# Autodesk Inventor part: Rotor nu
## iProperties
Shininess: 64.0
Length Units: 11269
Angle Units: 11279
Time Units: 11290
Mass Units: 11283
Length Display Precision: 3
Angle Display Precision: 2
Compacted: True
Part Number: Rotor nu
Document SubType Name: Modeling
Created: 2005-01
Material: Par défaut
Designer: lolo (Laurent Moretti)
Density: 0.0
Volumn: 0.0
Area: 0.0
PropertySet Name: Model Information
Control State: 0
Master: False
Checked Out: False
Author: lolo (Laurent Moretti)
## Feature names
1. Révolution1 [Revolution]
2. Chanfrein1 [Chamfer]
3. Chanfrein2 [Chamfer]
4. Chanfrein3 [Chamfer]
5. Extrusion1
